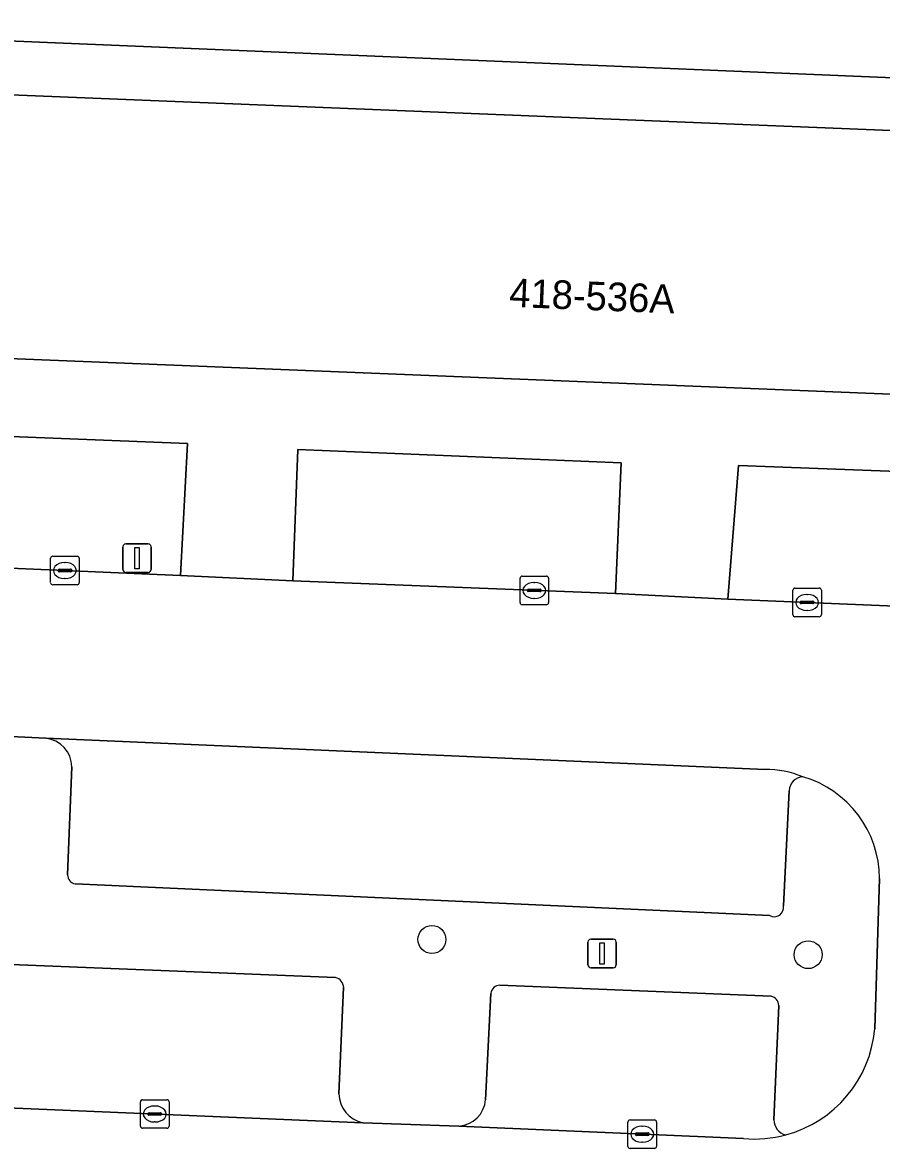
# Model space of a CAD drawing. Extents: x 160786 to 161429, y 386828 to 387485.
# Drawn here: x 160892.43 to 160922.5, y 387391.87 to 387431.29 of the extents above; entities that cross this region are included whole.
import ezdxf

# ---------------------------------------------------------------- set-up
doc = ezdxf.new("R2010")
doc.units = 0
for name, color, linetype in [('IMGEO_Boom', 7, 'Continuous'), ('IMGEO_Erf', 7, 'Continuous'), ('IMGEO_Groenvoorziening', 7, 'Continuous'), ('IMGEO_Kolk', 7, 'Continuous'), ('IMGEO_Lichtmast', 7, 'Continuous'), ('IMGEO_Pand', 7, 'Continuous'), ('IMGEO_Pand_nummerreeks', 7, 'Continuous'), ('IMGEO_Pand_overbouw', 7, 'Continuous'), ('IMGEO_Parkeervlak_open', 7, 'Continuous'), ('IMGEO_Rijbaan_lokaal_open', 7, 'Continuous'), ('IMGEO_Voetpad_open', 7, 'Continuous')]:
    doc.layers.add(name, color=color, linetype=linetype)

msp = doc.modelspace()

# ---------------------------------------------------------------- linework, layer by layer
at = {"layer": 'IMGEO_Boom'}
for centre in [(160906.757, 387399.186), (160919.929, 387398.654)]:
    msp.add_circle(centre, 0.489, dxfattribs=at)
at = {"layer": 'IMGEO_Erf'}
msp.add_lwpolyline([(160876.53, 387431.288), (160876.507, 387430.723), (160876.453, 387429.381), (160951.336, 387426.355), (160951.409, 387428.163)], close=True, dxfattribs=at)
at = {"layer": 'IMGEO_Groenvoorziening'}
for points in [[(160880.341, 387412.684), (160897.959, 387411.93), (160898.206, 387416.548), (160880.542, 387417.252)], [(160913.186, 387411.293), (160913.378, 387415.871), (160902.066, 387416.343), (160901.891, 387411.742)], [(160933.593, 387410.406), (160934.52, 387410.419), (160934.627, 387410.404), (160934.843, 387415.123), (160917.487, 387415.781), (160917.118, 387411.105)]]:
    msp.add_lwpolyline(points, close=True, dxfattribs=at)
for points in [[(160893.24, 387406.231), (160890.037, 387406.389)], [(160894.002, 387401.451), (160894.156, 387405.234)], [(160919.26, 387404.396), (160919.066, 387400.364)], [(160918.583, 387400.026), (160894.271, 387401.137)], [(160922.26, 387396.053), (160922.43, 387401.321)], [(160879.2, 387398.827), (160903.382, 387397.852)], [(160903.668, 387397.505), (160903.501, 387393.787)], [(160909.137, 387397.584), (160918.633, 387397.2)], [(160908.638, 387393.578), (160908.816, 387397.301)], [(160918.9, 387396.879), (160918.732, 387392.873)], [(160904.335, 387392.77), (160907.702, 387392.65)]]:
    msp.add_lwpolyline(points, dxfattribs=at)
for centre, radius, start, end in [((160893.126, 387405.207), 1.03, 1.4816, 83.6693), ((160919.78, 387404.363), 0.521, 94.2229, 176.3684), ((160918.698, 387401.3), 3.732, 0.3236, 73.7551), ((160894.321, 387401.452), 0.319, 180.1211, 261.0515), ((160918.745, 387400.309), 0.326, 240.2036, 9.7646), ((160903.291, 387397.485), 0.378, 2.9695, 76.0217), ((160909.141, 387397.256), 0.328, 90.7053, 172.0948), ((160918.558, 387396.866), 0.342, 2.1887, 77.3171), ((160918.066, 387396.419), 4.21, 284.8225, 355.0148), ((160904.566, 387393.81), 1.066, 181.2526, 257.455), ((160907.629, 387393.66), 1.012, 274.1281, 355.3801), ((160919.254, 387392.859), 0.522, 178.4642, 257.7536)]:
    msp.add_arc(centre, radius, start, end, dxfattribs=at)
at = {"layer": 'IMGEO_Kolk'}
for p, q in [((160893.408, 387411.678), (160893.408, 387412.53)), ((160893.483, 387412.604), (160894.335, 387412.604)), ((160894.409, 387412.53), (160894.409, 387411.678)), ((160893.667, 387412.098), (160893.667, 387412.11)), ((160894.105, 387412.061), (160893.707, 387412.061)), ((160893.71, 387412.147), (160894.108, 387412.147)), ((160893.896, 387412.384), (160893.921, 387412.384)), ((160894.151, 387412.11), (160894.151, 387412.098)), ((160893.919, 387411.824), (160893.894, 387411.824)), ((160909.842, 387410.98), (160909.842, 387411.832)), ((160909.917, 387411.906), (160910.769, 387411.906)), ((160910.33, 387411.686), (160910.355, 387411.686)), ((160910.843, 387411.832), (160910.843, 387410.98)), ((160894.335, 387411.604), (160893.483, 387411.604)), ((160910.101, 387411.4), (160910.101, 387411.412)), ((160910.539, 387411.363), (160910.141, 387411.363)), ((160910.144, 387411.449), (160910.542, 387411.449)), ((160910.585, 387411.412), (160910.585, 387411.4)), ((160919.392, 387410.561), (160919.392, 387411.413)), ((160919.467, 387411.487), (160920.319, 387411.487)), ((160919.88, 387411.267), (160919.905, 387411.267)), ((160920.393, 387411.413), (160920.393, 387410.561)), ((160910.769, 387410.906), (160909.917, 387410.906)), ((160910.353, 387411.126), (160910.328, 387411.126)), ((160919.651, 387410.981), (160919.651, 387410.993)), ((160920.089, 387410.944), (160919.691, 387410.944)), ((160919.694, 387411.03), (160920.092, 387411.03)), ((160920.135, 387410.993), (160920.135, 387410.981)), ((160920.319, 387410.487), (160919.467, 387410.487)), ((160919.903, 387410.707), (160919.878, 387410.707)), ((160896.553, 387392.651), (160896.553, 387393.503)), ((160896.628, 387393.577), (160897.48, 387393.577)), ((160897.554, 387393.503), (160897.554, 387392.651)), ((160896.855, 387393.12), (160897.253, 387393.12)), ((160897.041, 387393.357), (160897.066, 387393.357)), ((160896.812, 387393.071), (160896.812, 387393.083)), ((160897.25, 387393.034), (160896.852, 387393.034)), ((160897.064, 387392.797), (160897.039, 387392.797)), ((160897.296, 387393.083), (160897.296, 387393.071)), ((160913.621, 387391.944), (160913.621, 387392.796)), ((160913.696, 387392.87), (160914.548, 387392.87)), ((160914.622, 387392.796), (160914.622, 387391.944)), ((160897.48, 387392.577), (160896.628, 387392.577)), ((160913.88, 387392.364), (160913.88, 387392.376)), ((160914.318, 387392.327), (160913.92, 387392.327)), ((160913.923, 387392.413), (160914.321, 387392.413)), ((160914.109, 387392.65), (160914.134, 387392.65)), ((160914.364, 387392.376), (160914.364, 387392.364)), ((160914.132, 387392.09), (160914.107, 387392.09)), ((160914.548, 387391.87), (160913.696, 387391.87))]:
    msp.add_line(p, q, dxfattribs=at)
for points in [[(160893.408, 387411.678), (160893.408, 387412.53)], [(160893.483, 387412.604), (160894.335, 387412.604)], [(160894.409, 387412.53), (160894.409, 387411.678)], [(160909.842, 387410.98), (160909.842, 387411.832)], [(160909.917, 387411.906), (160910.769, 387411.906)], [(160910.843, 387411.832), (160910.843, 387410.98)], [(160894.335, 387411.604), (160893.483, 387411.604)], [(160919.392, 387410.561), (160919.392, 387411.413)], [(160919.467, 387411.487), (160920.319, 387411.487)], [(160920.393, 387411.413), (160920.393, 387410.561)], [(160910.769, 387410.906), (160909.917, 387410.906)], [(160920.319, 387410.487), (160919.467, 387410.487)], [(160896.553, 387392.651), (160896.553, 387393.503)], [(160896.628, 387393.577), (160897.48, 387393.577)], [(160897.554, 387393.503), (160897.554, 387392.651)], [(160913.621, 387391.944), (160913.621, 387392.796)], [(160913.696, 387392.87), (160914.548, 387392.87)], [(160914.622, 387392.796), (160914.622, 387391.944)], [(160897.48, 387392.577), (160896.628, 387392.577)], [(160914.548, 387391.87), (160913.696, 387391.87)]]:
    msp.add_lwpolyline(points, dxfattribs=at)
for centre, radius, start, end in [((160893.485, 387412.528), 0.0765, 91.552, 178.448), ((160893.485, 387412.528), 0.0765, 91.552, 178.448), ((160894.333, 387412.528), 0.0765, 1.552, 88.448), ((160894.333, 387412.528), 0.0765, 1.552, 88.448), ((160893.707, 387412.107), 0.0403, 85.8775, 175.7526), ((160893.704, 387412.097), 0.0366, 178.938, 274.7102), ((160894.108, 387412.104), 0.043, 264.8664, 352.4533), ((160894.112, 387412.109), 0.0386, 1.7309, 96.639), ((160893.485, 387411.68), 0.0765, 181.552, 268.448), ((160893.485, 387411.68), 0.0765, 181.552, 268.448), ((160894.333, 387411.68), 0.0765, 271.552, 358.448), ((160894.333, 387411.68), 0.0765, 271.552, 358.448), ((160909.919, 387411.83), 0.0765, 91.552, 178.448), ((160909.919, 387411.83), 0.0765, 91.552, 178.448), ((160910.767, 387411.83), 0.0765, 1.552, 88.448), ((160910.767, 387411.83), 0.0765, 1.552, 88.448), ((160910.141, 387411.409), 0.0403, 85.8775, 175.7526), ((160910.138, 387411.399), 0.0366, 178.938, 274.7102), ((160910.542, 387411.406), 0.043, 264.8664, 352.4533), ((160910.546, 387411.411), 0.0386, 1.7309, 96.639), ((160919.469, 387411.411), 0.0765, 91.552, 178.448), ((160919.469, 387411.411), 0.0765, 91.552, 178.448), ((160920.317, 387411.411), 0.0765, 1.552, 88.448), ((160920.317, 387411.411), 0.0765, 1.552, 88.448), ((160909.919, 387410.982), 0.0765, 181.552, 268.448), ((160909.919, 387410.982), 0.0765, 181.552, 268.448), ((160910.767, 387410.982), 0.0765, 271.552, 358.448), ((160910.767, 387410.982), 0.0765, 271.552, 358.448), ((160919.691, 387410.99), 0.0403, 85.8775, 175.7526), ((160919.688, 387410.98), 0.0366, 178.938, 274.7102), ((160920.092, 387410.987), 0.043, 264.8664, 352.4533), ((160920.096, 387410.992), 0.0386, 1.7309, 96.639), ((160919.469, 387410.563), 0.0765, 181.552, 268.448), ((160919.469, 387410.563), 0.0765, 181.552, 268.448), ((160920.317, 387410.563), 0.0765, 271.552, 358.448), ((160920.317, 387410.563), 0.0765, 271.552, 358.448), ((160896.63, 387393.501), 0.0765, 91.552, 178.448), ((160896.63, 387393.501), 0.0765, 91.552, 178.448), ((160897.478, 387393.501), 0.0765, 1.552, 88.448), ((160897.478, 387393.501), 0.0765, 1.552, 88.448), ((160896.852, 387393.08), 0.0403, 85.8775, 175.7526), ((160897.257, 387393.082), 0.0386, 1.7309, 96.639), ((160896.849, 387393.07), 0.0366, 178.938, 274.7102), ((160897.253, 387393.077), 0.043, 264.8664, 352.4533), ((160913.698, 387392.794), 0.0765, 91.552, 178.448), ((160913.698, 387392.794), 0.0765, 91.552, 178.448), ((160914.546, 387392.794), 0.0765, 1.552, 88.448), ((160914.546, 387392.794), 0.0765, 1.552, 88.448), ((160896.63, 387392.653), 0.0765, 181.552, 268.448), ((160896.63, 387392.653), 0.0765, 181.552, 268.448), ((160897.478, 387392.653), 0.0765, 271.552, 358.448), ((160897.478, 387392.653), 0.0765, 271.552, 358.448), ((160913.92, 387392.373), 0.0403, 85.8775, 175.7526), ((160913.917, 387392.363), 0.0366, 178.938, 274.7102), ((160914.321, 387392.37), 0.043, 264.8664, 352.4533), ((160914.325, 387392.375), 0.0386, 1.7309, 96.639), ((160913.698, 387391.946), 0.0765, 181.552, 268.448), ((160913.698, 387391.946), 0.0765, 181.552, 268.448), ((160914.546, 387391.946), 0.0765, 271.552, 358.448), ((160914.546, 387391.946), 0.0765, 271.552, 358.448)]:
    msp.add_arc(centre, radius, start, end, dxfattribs=at)
for centre, major_axis, ratio, start_param, end_param in [((160893.895, 387412.104), (-0.387, 0.002), 0.722429, 4.712389, 7.853982), ((160893.92, 387412.104), (-0.39, 0.002), 0.717154, 1.570796, 4.712389), ((160910.329, 387411.406), (-0.387, 0.002), 0.722429, 4.712389, 7.853982), ((160910.354, 387411.406), (-0.39, 0.002), 0.717154, 1.570796, 4.712389), ((160919.879, 387410.987), (-0.387, 0.002), 0.722429, 4.712389, 7.853982), ((160919.904, 387410.987), (-0.39, 0.002), 0.717154, 1.570796, 4.712389), ((160897.04, 387393.077), (-0.387, 0.002), 0.722429, 4.712389, 7.853982), ((160897.065, 387393.077), (-0.39, 0.002), 0.717154, 1.570796, 4.712389), ((160914.108, 387392.37), (-0.387, 0.002), 0.722429, 4.712389, 7.853982), ((160914.133, 387392.37), (-0.39, 0.002), 0.717154, 1.570796, 4.712389)]:
    msp.add_ellipse(centre, major_axis=major_axis, ratio=ratio, start_param=start_param, end_param=end_param, dxfattribs=at)
at = {"layer": 'IMGEO_Lichtmast'}
for p, q in [((160895.938, 387412.137), (160895.938, 387412.937)), ((160895.938, 387412.937), (160895.938, 387412.137)), ((160896.038, 387413.037), (160896.828, 387413.037)), ((160896.828, 387413.037), (160896.038, 387413.037)), ((160896.928, 387412.937), (160896.928, 387412.137)), ((160896.928, 387412.137), (160896.928, 387412.937)), ((160896.828, 387412.037), (160896.038, 387412.037)), ((160896.038, 387412.037), (160896.828, 387412.037)), ((160912.218, 387398.297), (160912.218, 387399.097)), ((160912.218, 387399.097), (160912.218, 387398.297)), ((160912.318, 387399.197), (160913.108, 387399.197)), ((160913.108, 387399.197), (160912.318, 387399.197)), ((160913.208, 387399.097), (160913.208, 387398.297)), ((160913.208, 387398.297), (160913.208, 387399.097)), ((160913.108, 387398.197), (160912.318, 387398.197)), ((160912.318, 387398.197), (160913.108, 387398.197))]:
    msp.add_line(p, q, dxfattribs=at)
for points in [[(160896.358, 387412.912), (160896.508, 387412.912), (160896.508, 387412.162), (160896.358, 387412.162), (160896.358, 387412.912)], [(160912.638, 387399.072), (160912.788, 387399.072), (160912.788, 387398.322), (160912.638, 387398.322), (160912.638, 387399.072)]]:
    msp.add_lwpolyline(points, dxfattribs=at)
for centre, start, end in [((160896.038, 387412.937), 90, 180), ((160896.038, 387412.937), 90, 180), ((160896.828, 387412.937), 0, 90), ((160896.828, 387412.937), 360, 90), ((160896.038, 387412.137), 180, 270), ((160896.038, 387412.137), 180, 270), ((160896.828, 387412.137), 270, 0), ((160896.828, 387412.137), 270, 0), ((160912.318, 387399.097), 90, 180), ((160912.318, 387399.097), 90, 180), ((160913.108, 387399.097), 0, 90), ((160913.108, 387399.097), 360, 90), ((160912.318, 387398.297), 180, 270), ((160912.318, 387398.297), 180, 270), ((160913.108, 387398.297), 270, 0), ((160913.108, 387398.297), 270, 0)]:
    msp.add_arc(centre, 0.1, start, end, dxfattribs=at)
at = {"layer": 'IMGEO_Pand'}
msp.add_lwpolyline([(160954.238, 387420.345), (160954.549, 387428.036), (160951.409, 387428.163), (160951.336, 387426.355), (160876.453, 387429.381), (160876.42, 387428.554), (160876.08, 387420.163), (160937.531, 387417.68), (160950.986, 387417.136), (160951.121, 387420.469), (160951.171, 387421.697), (160953.724, 387421.594), (160953.674, 387420.367)], close=True, dxfattribs=at)
at = {"layer": 'IMGEO_Pand_overbouw'}
msp.add_lwpolyline([(160951.409, 387428.163), (160876.53, 387431.288), (160876.507, 387430.723), (160876.453, 387429.381), (160951.336, 387426.355)], close=True, dxfattribs=at)
at = {"layer": 'IMGEO_Parkeervlak_open'}
for points in [[(160918.42, 387405.14), (160893.24, 387406.231)], [(160894.156, 387405.234), (160894.002, 387401.451)], [(160919.066, 387400.364), (160919.26, 387404.396)], [(160894.271, 387401.137), (160918.583, 387400.026)], [(160903.382, 387397.852), (160879.2, 387398.827)], [(160903.501, 387393.787), (160903.668, 387397.505)], [(160918.633, 387397.2), (160909.137, 387397.584)], [(160908.816, 387397.301), (160908.638, 387393.578)], [(160918.732, 387392.873), (160918.9, 387396.879)], [(160879.713, 387393.809), (160904.335, 387392.77)], [(160907.702, 387392.65), (160917.669, 387392.215)]]:
    msp.add_lwpolyline(points, dxfattribs=at)
for centre, radius, start, end in [((160893.126, 387405.207), 1.03, 1.4816, 83.6693), ((160918.439, 387401.712), 3.429, 67.672, 90.3255), ((160919.78, 387404.363), 0.521, 94.2229, 176.3684), ((160894.321, 387401.452), 0.319, 180.1211, 261.0515), ((160918.745, 387400.309), 0.326, 240.2036, 9.7646), ((160903.291, 387397.485), 0.378, 2.9695, 76.0217), ((160909.141, 387397.256), 0.328, 90.7053, 172.0948), ((160918.558, 387396.866), 0.342, 2.1887, 77.3171), ((160904.566, 387393.81), 1.066, 181.2526, 257.455), ((160907.629, 387393.66), 1.012, 274.1281, 355.3801), ((160919.254, 387392.859), 0.522, 178.4642, 257.7536), ((160918.035, 387396.364), 4.165, 264.9598, 285.4291)]:
    msp.add_arc(centre, radius, start, end, dxfattribs=at)
at = {"layer": 'IMGEO_Rijbaan_lokaal_open'}
for points in [[(160931.719, 387404.777), (160933.298, 387404.761), (160933.593, 387410.406), (160917.118, 387411.105), (160913.186, 387411.293), (160901.891, 387411.742), (160897.959, 387411.93), (160880.341, 387412.684), (160875.756, 387412.901), (160874.782, 387412.927)], [(160879.264, 387406.819), (160890.037, 387406.389), (160893.24, 387406.231), (160918.42, 387405.14)], [(160922.43, 387401.321), (160922.26, 387396.053)], [(160917.669, 387392.215), (160907.702, 387392.65), (160904.335, 387392.77), (160879.713, 387393.809)]]:
    msp.add_lwpolyline(points, dxfattribs=at)
for centre, radius, start, end in [((160918.439, 387401.712), 3.429, 67.672, 90.3255), ((160918.698, 387401.3), 3.732, 0.3236, 73.7551), ((160918.066, 387396.419), 4.21, 284.8225, 355.0148), ((160918.035, 387396.364), 4.165, 264.9598, 285.4291)]:
    msp.add_arc(centre, radius, start, end, dxfattribs=at)
at = {"layer": 'IMGEO_Voetpad_open'}
msp.add_lwpolyline([(160876.08, 387420.163), (160876.42, 387428.554), (160876.453, 387429.381), (160876.507, 387430.723), (160876.53, 387431.288), (160951.409, 387428.163), (160954.549, 387428.036), (160954.238, 387420.345), (160953.674, 387420.367), (160951.121, 387420.469), (160950.986, 387417.136), (160937.531, 387417.68)], close=True, dxfattribs=at)
msp.add_lwpolyline([(160872.083, 387413.482), (160872.162, 387414.185), (160875.882, 387414.001), (160875.756, 387412.901), (160880.341, 387412.684), (160880.542, 387417.252), (160898.206, 387416.548), (160897.959, 387411.93), (160901.891, 387411.742), (160902.066, 387416.343), (160913.378, 387415.871), (160913.186, 387411.293), (160917.118, 387411.105), (160917.487, 387415.781), (160934.843, 387415.123), (160934.627, 387410.404), (160934.52, 387410.419), (160934.225, 387404.654), (160933.298, 387404.761), (160931.719, 387404.777)], dxfattribs=at)

# ---------------------------------------------------------------- texts
at = {"layer": 'IMGEO_Pand_nummerreeks'}
msp.add_text('418-536A', height=1, rotation=357.6859, dxfattribs=at).set_placement((160909.448, 387421.336))

doc.saveas('drawing.dxf')
